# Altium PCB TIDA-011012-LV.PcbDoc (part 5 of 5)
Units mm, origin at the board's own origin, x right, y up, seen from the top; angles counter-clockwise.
Board outline 250 x 280 mm, 4 copper layers (Top Layer, Layer 1, Layer 2, Bottom Layer), stack 2.208 mm thick; 410 components, 230 nets, 1280 pads, 1868 vias.
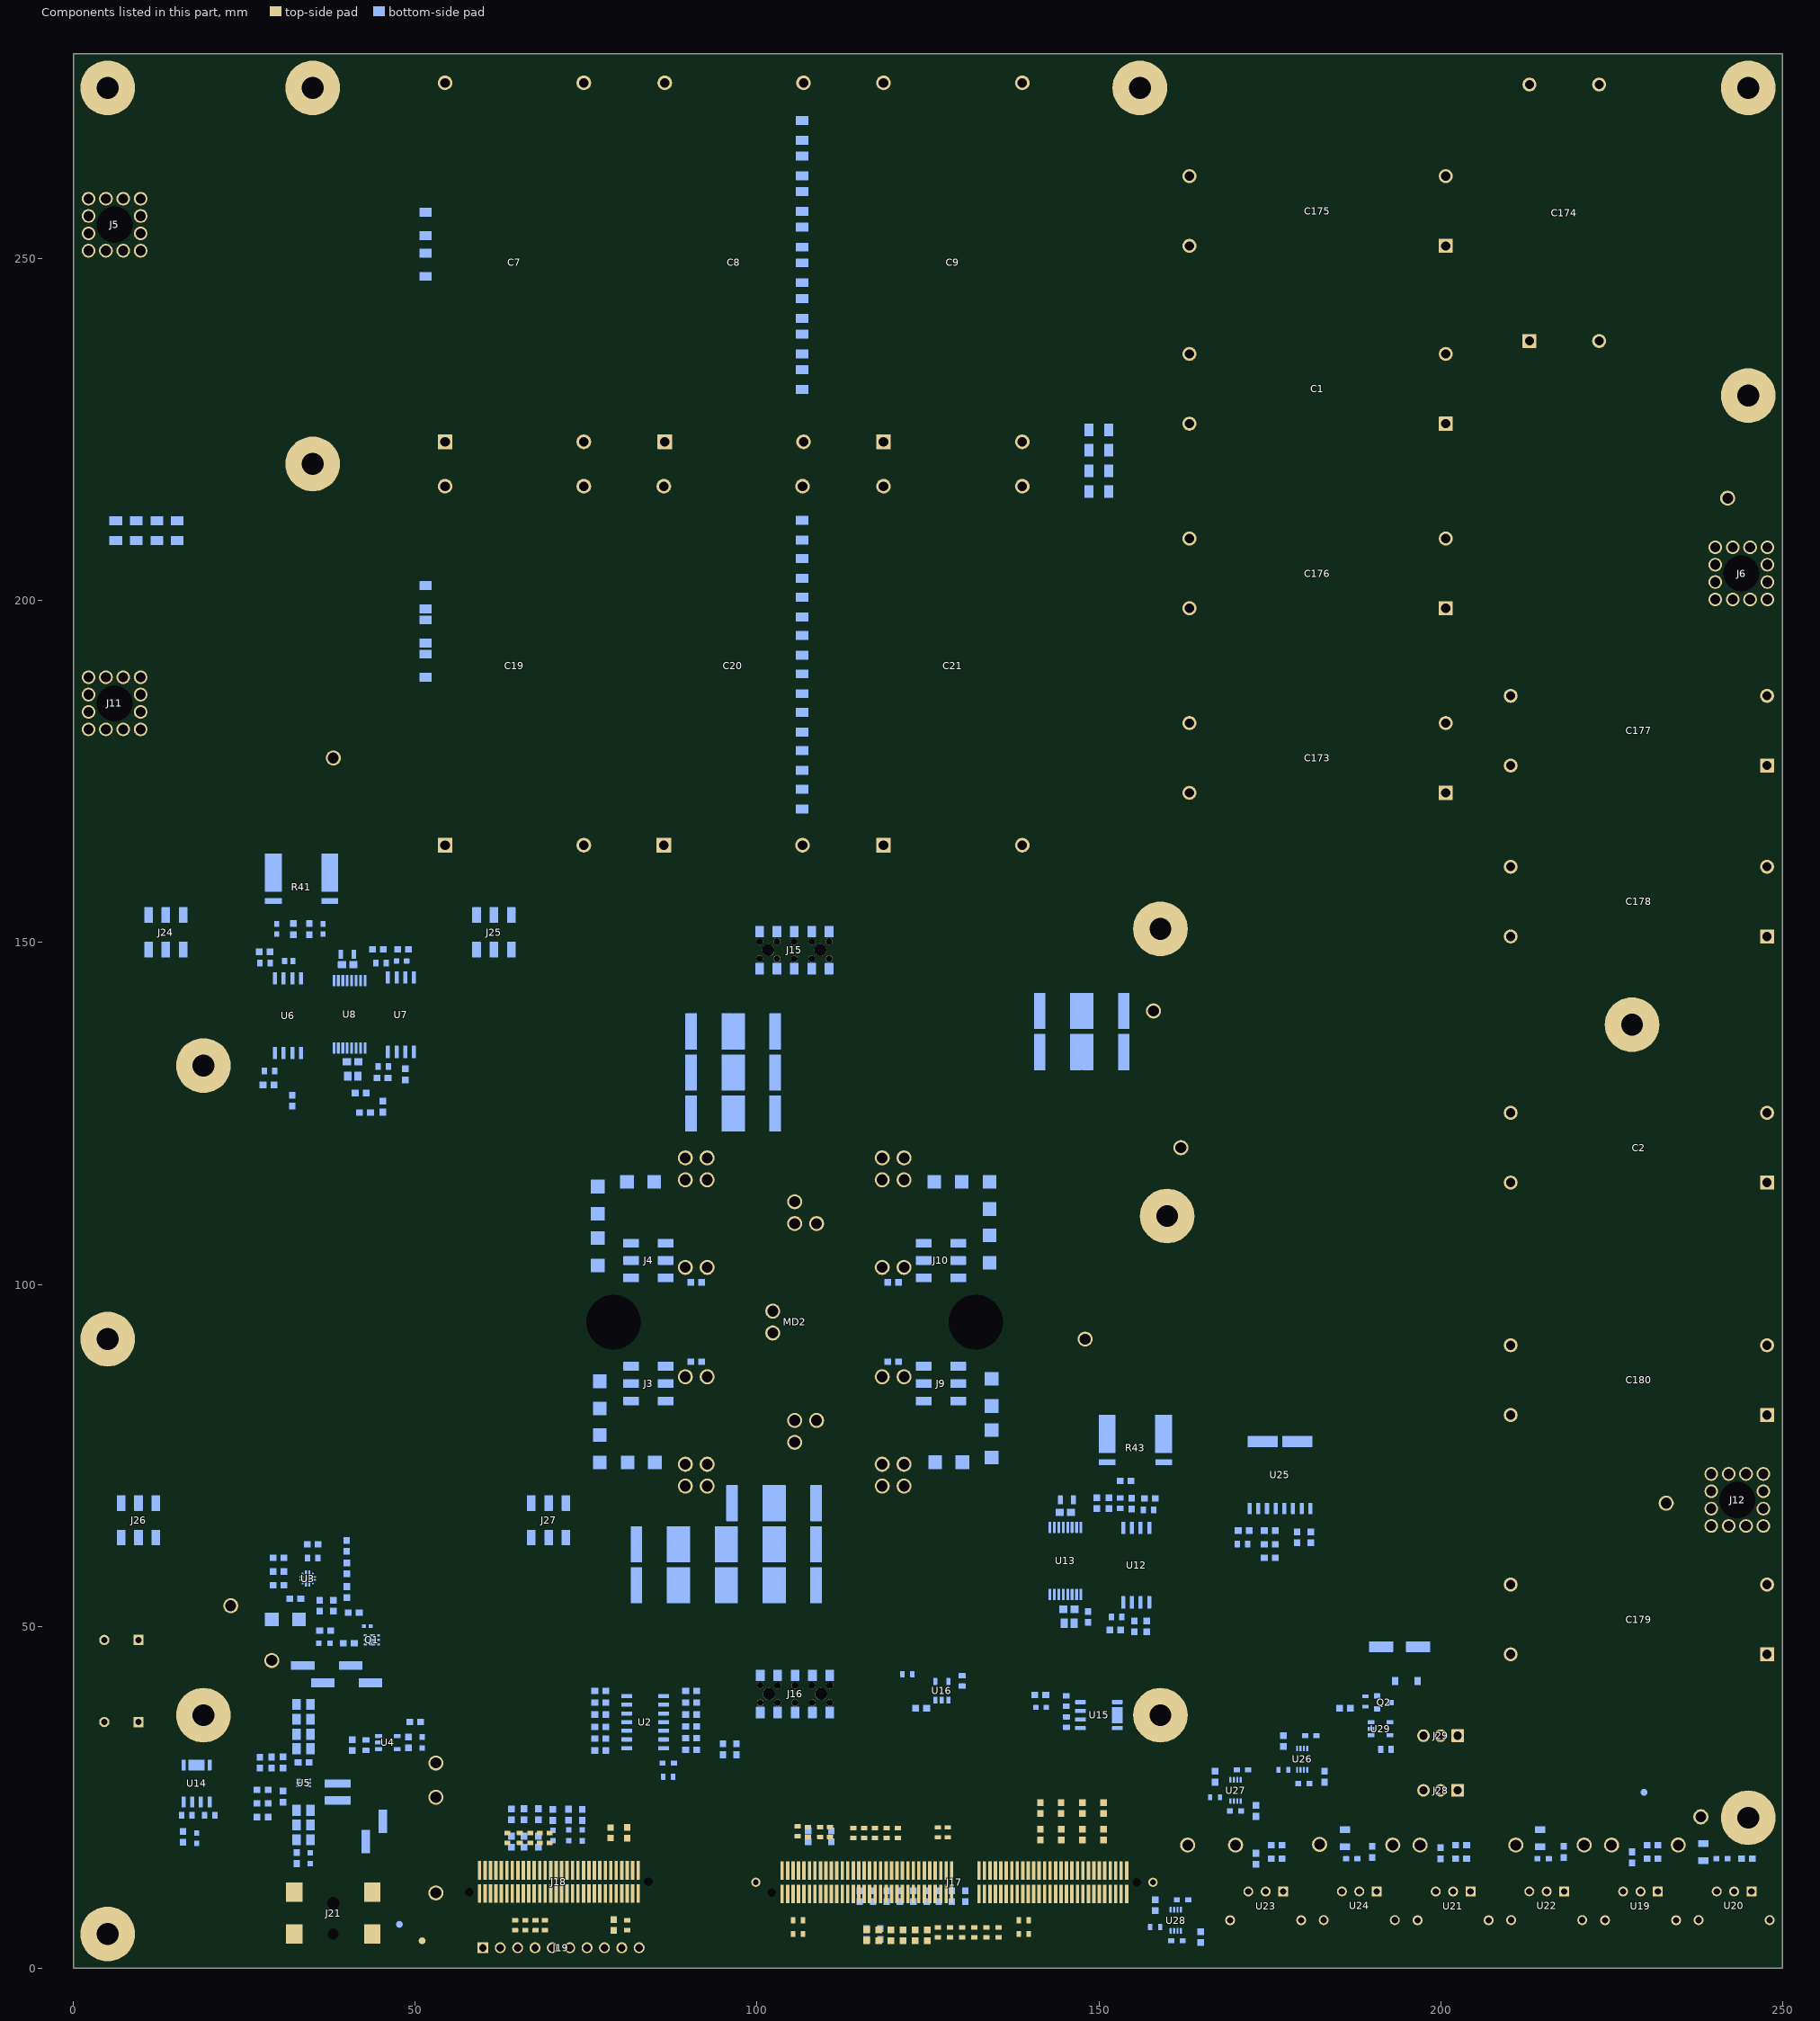
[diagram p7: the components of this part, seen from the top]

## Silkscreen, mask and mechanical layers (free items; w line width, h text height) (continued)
M11 Gerber Information:
  lines w0.254: -17.917,-44.026 149.723,-44.026 ; -17.917,-38.862 149.774,-38.862 ; -17.917,-33.697 -17.917,-49.191 83.81,-49.191 149.774,-49.191 149.774,-33.697 -17.904,-33.697 -17.904,-49.191 22.114,-49.191 ; 44.694,-49.191 44.694,-33.697 ; 76.876,-38.862 76.876,-33.697 ; 98.212,-38.862 98.212,-33.697 ; 114.011,-49.356 114.011,-44.204
  text "ALL ARTWORK VIEWED FROM TOP SIDE" at -16.304,-37.054 h1.52
  text "BOARD #:" at 46.599,-37.054 h1.52
  text ".PRJ_Number" at 60.455,-37.054 h1.52
  text "REV:" at 81.905,-37.054 h1.52
  text ".PCB_Rev" at 89.309,-37.054 h1.52
  text "SVN REV:" at 103.19,-37.054 h1.52
  text ".VersionControl_RevNumber" at 116.043,-37.054 h1.52
  text "LAYER NAME =" at -16.304,-42.206 h1.52
  text "PLOT NAME =" at -16.304,-47.434 h1.52
  text ".plot_File_Name" at 4.156,-47.434 h1.52
  text "GENERATED    :" at 46.65,-47.434 h1.52
  text ".Print_Date" at 68.735,-47.434 h1.52
  text ".Print_Time" at 87.252,-47.434 h1.52
  text "TEXAS INSTRUMENTS" at 119.37,-47.434 h1.52
M12 Stackup:
  text ".Layer_Name" at 4.156,-42.206 h1.52
M13 Component Bodies Top:
  text ".Layer_Name" at 4.156,-42.206 h1.52
M14 Component Bodies Bottom:
  text ".Layer_Name" at 4.156,-42.206 h1.52
M15 Courtyards Top:
  text ".Layer_Name" at 4.156,-42.206 h1.52
M16 Courtyards Bottom:
  text ".Layer_Name" at 4.156,-42.206 h1.52
Drill Drawing:
  text ".Layer_Name" at 4.156,-42.206 h1.52
M17 Embedded Cavity:
  text ".Layer_Name" at 4.156,-42.206 h1.52
M18 Embedded Assembly:
  text ".Layer_Name" at 4.156,-42.206 h1.52
M19 Embedded Keepout:
  text ".Layer_Name" at 4.41,-41.952 h1.52

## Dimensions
-10.5,-30.56 to 14.9,-30.56 on M2 Board Dimensions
